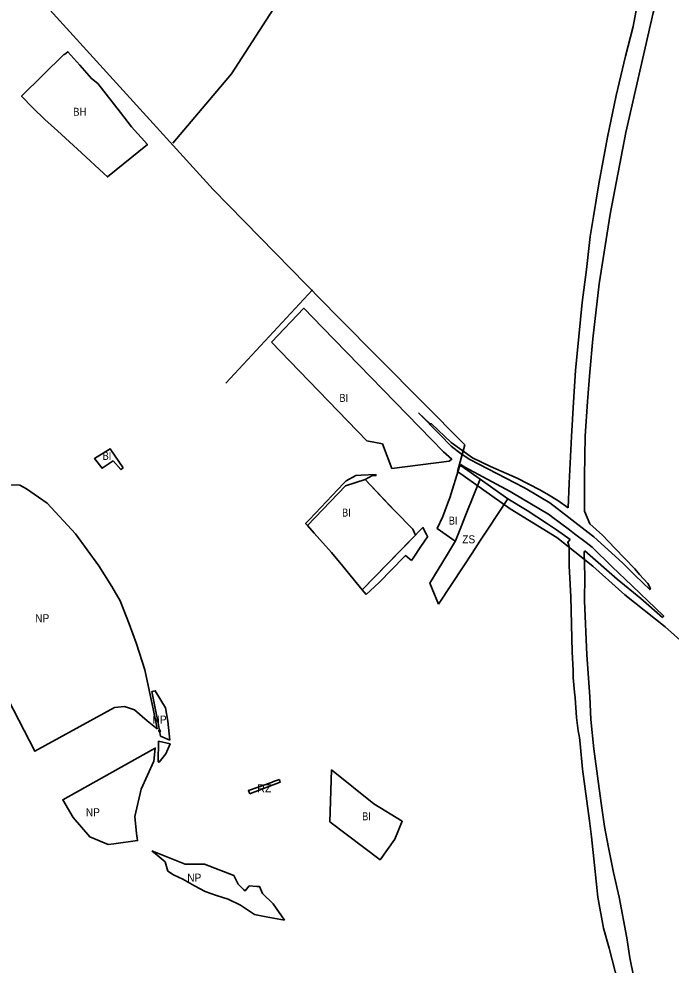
# Model space of a CAD drawing. Extents: x -650276 to -642489, y -1074311 to -1066658.
# Drawn here: x -646196 to -645218, y -1073124 to -1071706 of the extents above; entities that cross this region are included whole.
import ezdxf

# ---------------------------------------------------------------- set-up
doc = ezdxf.new("R2010")
doc.units = 0
doc.header["$LTSCALE"] = 4.8
doc.header["$PDMODE"] = 32
doc.header["$PDSIZE"] = 2.4
for name, color, linetype, lineweight in [('1', 7, 'Continuous', 35), ('15', 7, 'Continuous', 35), ('2', 7, 'Continuous', 35), ('24', 7, 'Continuous', 35), ('41', 7, 'Continuous', 35), ('48', 7, 'Continuous', 35), ('54', 7, 'Continuous', 35), ('6', 7, 'Continuous', 35)]:
    doc.layers.add(name, color=color, linetype=linetype, lineweight=lineweight)
doc.layers.add('62', color=7, linetype='Continuous')
doc.layers.add('63', color=7, linetype='Continuous')

msp = doc.modelspace()

# ---------------------------------------------------------------- linework, layer by layer
at = {"layer": '1'}
msp.add_lwpolyline([(-646102.04, -1071906.4), (-646068.317, -1071937.555), (-646062.91, -1071942.55), (-646002.93, -1071893.984), (-646026.64, -1071867.44), (-646043.49, -1071845.87), (-646077.32, -1071802.59), (-646087, -1071795), (-646104.5, -1071774.86), (-646122.16, -1071754.78), (-646127.12, -1071759.15), (-646127.84, -1071758.53), (-646191.57, -1071821.44), (-646174.69, -1071838.69), (-646156.59, -1071856.53), (-646137.74, -1071873.31)], close=True, dxfattribs=at)
at = {"layer": '15'}
for points in [[(-645661.3, -1072388.74), (-645682.59, -1072389.76), (-645690.37, -1072390.13), (-645705, -1072398.19), (-645708.94, -1072402.11)], [(-645676.53, -1072396.16), (-645676.53, -1072396.16), (-645665.32, -1072390.32), (-645660.16, -1072389.95), (-645661.3, -1072388.74)], [(-645708.94, -1072402.11), (-645760.02, -1072455.94), (-645765.95, -1072462.03), (-645763.06, -1072465.26)], [(-645763.06, -1072465.26), (-645706.039, -1072405.769), (-645676.53, -1072396.16)], [(-645582.84, -1072481.71), (-645584.46, -1072478.58), (-645589.862, -1072468.109), (-645680.87, -1072561.42), (-645675.13, -1072568.36)], [(-645607.07, -1072517.61), (-645605.95, -1072515.95), (-645604.82, -1072514.3), (-645592.9, -1072496.52), (-645583.13, -1072482.13), (-645582.84, -1072481.71)], [(-645675.13, -1072568.36), (-645655.65, -1072550.62), (-645617.87, -1072512.12), (-645615.95, -1072510.16), (-645607.07, -1072517.61)]]:
    msp.add_lwpolyline(points, dxfattribs=at)
at = {"layer": '2'}
msp.add_line((-645553.35, -1072508.1), (-645541.09, -1072487.98), dxfattribs=at)
for points in [[(-645817.219, -1072189.975), (-645768.649, -1072139.283), (-645740.45, -1072168.23), (-645559.34, -1072354.42), (-645546.82, -1072365.72), (-645550.41, -1072368.47), (-645636.37, -1072379.57), (-645650.78, -1072342.73), (-645674, -1072338), (-645789.298, -1072218.833)], [(-645729.36, -1072909.65), (-645654.16, -1072966.3), (-645632.23, -1072935.28), (-645620.92, -1072908.65), (-645663.52, -1072882.58), (-645726.9, -1072831.5)]]:
    msp.add_lwpolyline(points, close=True, dxfattribs=at)
for points in [[(-646039.16, -1072378.43), (-646058.64, -1072350.29), (-646082.55, -1072364.84), (-646071, -1072379.27), (-646054.43, -1072368.34)], [(-646054.43, -1072368.34), (-646042.65, -1072381.23), (-646039.16, -1072378.43)], [(-645541.09, -1072487.98), (-645533.15, -1072468.21), (-645524.87, -1072447.61), (-645503.98, -1072395.64), (-645532.75, -1072375.41), (-645535.05, -1072376.72), (-645549.6, -1072423.39), (-645551.54, -1072428.66), (-645559.92, -1072451.41), (-645568.38, -1072469.68), (-645541.56, -1072488.74)], [(-645632.1, -1072442.93), (-645676.53, -1072396.16), (-645706.039, -1072405.769), (-645763.06, -1072465.26), (-645753.128, -1072476.383), (-645744.38, -1072486.18), (-645726.95, -1072505.7), (-645709.92, -1072526.3), (-645694.51, -1072544.93), (-645680.87, -1072561.42), (-645600.883, -1072479.409)], [(-645632.1, -1072442.93), (-645638.82, -1072435.99), (-645676.53, -1072396.16), (-645706.039, -1072405.769), (-645763.06, -1072465.26), (-645753.128, -1072476.383)], [(-645600.945, -1072479.473), (-645605.17, -1072470.52), (-645632.1, -1072442.93)], [(-645753.128, -1072476.383), (-645744.38, -1072486.18), (-645726.95, -1072505.7), (-645709.92, -1072526.3)], [(-645709.92, -1072526.3), (-645694.51, -1072544.93), (-645680.87, -1072561.42), (-645600.945, -1072479.473)]]:
    msp.add_lwpolyline(points, dxfattribs=at)
at = {"layer": '24'}
for points in [[(-645339.904, -1072462.677), (-645347.551, -1072443.527), (-645347.677, -1072391.355), (-645346.62, -1072330.914), (-645343.458, -1072278.998), (-645339.908, -1072235.158), (-645335.367, -1072185.207), (-645325.498, -1072102.789), (-645309.01, -1071998.147), (-645285.617, -1071875.733), (-645244.798, -1071696.585), (-645235.793, -1071663.703), (-645230.436, -1071634.261), (-645227.905, -1071625.277), (-645222.48, -1071606.08)], [(-645339.904, -1072462.677), (-645347.551, -1072443.527), (-645347.677, -1072391.355), (-645346.62, -1072330.914), (-645343.458, -1072278.998), (-645339.908, -1072235.158), (-645335.367, -1072185.207), (-645325.498, -1072102.789), (-645309.01, -1071998.147), (-645285.617, -1071875.733), (-645244.798, -1071696.585), (-645235.793, -1071663.703), (-645230.436, -1071634.261), (-645227.905, -1071625.277), (-645222.48, -1071606.08)], [(-645255.662, -1071626.67), (-645261.094, -1071645.025), (-645264.841, -1071657.687), (-645269.077, -1071687.396), (-645274.868, -1071717.176), (-645286.175, -1071761.228), (-645300.076, -1071820.179), (-645313.153, -1071883.081), (-645326.343, -1071952.807)], [(-645255.662, -1071626.67), (-645261.094, -1071645.025), (-645264.841, -1071657.687), (-645269.077, -1071687.396), (-645274.868, -1071717.176), (-645286.175, -1071761.228), (-645300.076, -1071820.179), (-645313.153, -1071883.081)], [(-645313.153, -1071883.081), (-645326.343, -1071952.807), (-645334.118, -1072001.954), (-645339.455, -1072031.565), (-645344.819, -1072081.225), (-645351.358, -1072130.815), (-645361.317, -1072232.824), (-645364.435, -1072280.268), (-645366.951, -1072331.609), (-645370.624, -1072401.447), (-645372.228, -1072438.764)], [(-645326.343, -1071952.807), (-645334.118, -1072001.954), (-645339.455, -1072031.565), (-645344.819, -1072081.225), (-645351.358, -1072130.815), (-645361.317, -1072232.824), (-645364.435, -1072280.268), (-645366.951, -1072331.609), (-645370.624, -1072401.447), (-645372.228, -1072438.764)], [(-645372.228, -1072438.764), (-645387.894, -1072427.453), (-645401.441, -1072419.033), (-645414.631, -1072411.611), (-645448.831, -1072394.325), (-645488.64, -1072376.782), (-645515.437, -1072363.447), (-645547.593, -1072340.827), (-645577.33, -1072312.704), (-645579.217, -1072312.425), (-645596.405, -1072296.114)], [(-645596.405, -1072296.114), (-645564.4, -1072328.61), (-645547.72, -1072346.19), (-645532.07, -1072358.01), (-645531.65, -1072358.29), (-645528.27, -1072360.53), (-645519.57, -1072366.3), (-645438.64, -1072408.1)], [(-645372.228, -1072438.764), (-645387.894, -1072427.453), (-645401.441, -1072419.033), (-645414.631, -1072411.611), (-645448.831, -1072394.325), (-645488.64, -1072376.782), (-645515.437, -1072363.447), (-645547.593, -1072340.827), (-645577.33, -1072312.704), (-645579.217, -1072312.425), (-645596.405, -1072296.114)], [(-645596.405, -1072296.114), (-645564.4, -1072328.61), (-645547.72, -1072346.19), (-645532.07, -1072358.01), (-645531.65, -1072358.29), (-645528.27, -1072360.53), (-645519.57, -1072366.3), (-645438.64, -1072408.1)], [(-645462.646, -1072425.015), (-645503.98, -1072395.64), (-645532.75, -1072375.41), (-645534.3, -1072374.33), (-645533.08, -1072373.71)], [(-645533.08, -1072373.71), (-645527.33, -1072377.73), (-645459.31, -1072413.95), (-645456.52, -1072415.6), (-645400.12, -1072449.03), (-645396.94, -1072451.44), (-645370.226, -1072471.736)], [(-645438.64, -1072408.1), (-645437.6, -1072408.64), (-645434.19, -1072410.67), (-645399.77, -1072431.12), (-645371.356, -1072453.119), (-645342.284, -1072475.625)], [(-645438.64, -1072408.1), (-645437.6, -1072408.64), (-645434.19, -1072410.67), (-645399.77, -1072431.12), (-645371.356, -1072453.119), (-645342.284, -1072475.625), (-645333.62, -1072482.33), (-645290.76, -1072520.92)], [(-645369.364, -1072485.931), (-645389.731, -1072471.612), (-645404.64, -1072461.72), (-645433.91, -1072442.56), (-645462.646, -1072425.015)], [(-645370.226, -1072471.736), (-645362.81, -1072477.37), (-645345.079, -1072490.836)], [(-645290.76, -1072520.92), (-645271.74, -1072539.96), (-645249.9, -1072561.25), (-645248.967, -1072559.511), (-645252.768, -1072552.178), (-645265.009, -1072538.358), (-645272.276, -1072530.154), (-645302.303, -1072499.014), (-645320.805, -1072479.495), (-645339.904, -1072462.677)], [(-645290.76, -1072520.92), (-645271.74, -1072539.96), (-645249.9, -1072561.25), (-645248.967, -1072559.511), (-645252.768, -1072552.178), (-645265.009, -1072538.358), (-645272.276, -1072530.154), (-645302.303, -1072499.014), (-645320.805, -1072479.495), (-645339.904, -1072462.677)], [(-645364.524, -1072682.575), (-645366.022, -1072654.462), (-645368.173, -1072571.881), (-645370.755, -1072525.734), (-645370.928, -1072496.619), (-645372.72, -1072490.314), (-645369.364, -1072485.931)], [(-645342.284, -1072475.625), (-645333.62, -1072482.33), (-645290.76, -1072520.92)], [(-645347.292, -1072502.877), (-645348.253, -1072505.583), (-645347.214, -1072540.97), (-645347.795, -1072577.893), (-645344.152, -1072658.857), (-645339.96, -1072721.587), (-645338.023, -1072755.969), (-645333.718, -1072799.987)], [(-645230.845, -1072602.888), (-645263.217, -1072574.314), (-645298.498, -1072545.352), (-645347.292, -1072502.877)], [(-645345.079, -1072490.836), (-645336.33, -1072497.48), (-645306.46, -1072527.08), (-645276.93, -1072555.11), (-645263.7, -1072567.8), (-645242, -1072588.6), (-645241.87, -1072588.722), (-645228.96, -1072600.865), (-645230.845, -1072602.888)], [(-645357.272, -1072772.771), (-645359.76, -1072752.865), (-645361.874, -1072723.527), (-645362.708, -1072714.781), (-645364.786, -1072692.977), (-645364.524, -1072682.575)], [(-645271.518, -1073261.16), (-645272.747, -1073256.762), (-645275.269, -1073240.71), (-645276.125, -1073226.571), (-645288.647, -1073184.518), (-645297.395, -1073151.294), (-645310.558, -1073098.946), (-645319.052, -1073068.6), (-645327.554, -1073022.214), (-645332.517, -1072974.538), (-645337.34, -1072932.073), (-645340.345, -1072908.029), (-645350.822, -1072830.388), (-645354.019, -1072792.454), (-645355.121, -1072782.993), (-645357.272, -1072772.771)], [(-645333.718, -1072799.987), (-645327.091, -1072848.387), (-645322.284, -1072885.085), (-645317.65, -1072916.642)], [(-645317.65, -1072916.642), (-645311.772, -1072947.945), (-645304.24, -1072985.372), (-645295.788, -1073022.556)], [(-645295.788, -1073022.556), (-645284.269, -1073083.286), (-645279.878, -1073113.356), (-645262.388, -1073199.409), (-645257.842, -1073221.36), (-645247.051, -1073248.736), (-645239.9, -1073270.025), (-645226.847, -1073278.345), (-645227.199, -1073283.366), (-645227.744, -1073292.736)]]:
    msp.add_lwpolyline(points, dxfattribs=at)
at = {"layer": '41'}
msp.add_line((-645566.54, -1072582.88), (-645528.81, -1072525.54), dxfattribs=at)
msp.add_lwpolyline([(-645528.81, -1072525.54), (-645516.37, -1072506.64), (-645504.48, -1072488.58), (-645492.61, -1072470.54), (-645462.65, -1072425.01), (-645503.98, -1072395.64), (-645524.87, -1072447.61), (-645533.15, -1072468.21), (-645541.09, -1072487.98), (-645553.35, -1072508.1), (-645579.76, -1072551.45), (-645575.9, -1072560.13), (-645566.54, -1072582.88)], dxfattribs=at)
at = {"layer": '48'}
for points in [[(-646236.97, -1072678.31), (-646171.72, -1072803.51), (-646052.58, -1072737.82), (-646037.23, -1072736.38), (-646022.4, -1072741.58), (-646003.22, -1072757.85), (-645988.43, -1072769.93), (-645990.04, -1072761.78), (-645993.89, -1072742.23), (-646006.66, -1072681.4), (-646019.16, -1072642.35), (-646030.17, -1072612.31), (-646043.87, -1072578.12), (-646056.42, -1072556.49), (-646075.82, -1072525.54), (-646110.61, -1072477.49), (-646153.49, -1072431.54), (-646172.81, -1072418.2), (-646184.449, -1072410.256), (-646194.19, -1072404.62), (-646254.75, -1072404.25)], [(-645969.46, -1072787.03), (-645972.31, -1072758.48), (-645975.86, -1072738.61), (-645991.31, -1072712.86), (-645996.31, -1072714.11), (-645990.95, -1072741.65), (-645987.1, -1072761.2), (-645984.79, -1072772.91)], [(-645984.79, -1072772.91), (-645983.22, -1072780.88), (-645969.46, -1072787.03)], [(-645986.24, -1072788.33), (-645986.71, -1072819.26), (-645986.71, -1072819.26)], [(-645975.3, -1072807.37), (-645969.01, -1072792.28), (-645986.24, -1072788.33)], [(-645986.71, -1072819.26), (-645986.71, -1072819.26), (-645985.19, -1072819.72), (-645975.3, -1072807.37)], [(-645972.6, -1072983.41), (-645976.48, -1072969.55), (-645988.49, -1072959.28), (-645996.2, -1072952.69)], [(-645996.2, -1072952.69), (-645946.4, -1072973.05), (-645917.53, -1072972.93), (-645873.3, -1072989.79), (-645866.93, -1073002.72)], [(-645863.39, -1073034.25), (-645882.07, -1073025.22), (-645899.35, -1073019.65), (-645916.47, -1073014.03), (-645932.44, -1073005.5), (-645949.85, -1072995.57), (-645962.81, -1072989.45), (-645963.77, -1072989), (-645972.6, -1072983.41)], [(-645866.93, -1073002.72), (-645858.82, -1073010.74), (-645856.46, -1073013.07), (-645850.37, -1073005.42), (-645838.89, -1073006.18)], [(-645838.89, -1073006.18), (-645834.9, -1073006.45), (-645830.6, -1073016.92), (-645814.27, -1073032.11), (-645797.32, -1073056.62)], [(-645797.32, -1073056.62), (-645824.93, -1073051.83), (-645842.53, -1073048.19), (-645863.39, -1073034.25)]]:
    msp.add_lwpolyline(points, dxfattribs=at)
msp.add_lwpolyline([(-645993.47, -1072818.44), (-645991.37, -1072798.84), (-645996.8, -1072801.88), (-646129.91, -1072876.24), (-646114.5, -1072902.8), (-646089.39, -1072931.92), (-646062.04, -1072943.58), (-646053.287, -1072942.399), (-646017.65, -1072937.59), (-646019.21, -1072926.91), (-646021.64, -1072901.6), (-646012.37, -1072860.3)], close=True, dxfattribs=at)
msp.add_point((-645984.79, -1072772.91), dxfattribs=at)
at = {"layer": '54'}
msp.add_line((-645885.363, -1072251.506), (-645755.385, -1072111.972), dxfattribs=at)
for points in [[(-645648.577, -1071395.44), (-645803.784, -1071674.386), (-645877, -1071788), (-645965, -1071892)], [(-646336.784, -1071524.232), (-646218.737, -1071612.767), (-646164.374, -1071674.897), (-645904.456, -1071961.331), (-645718.199, -1072151.712), (-645526.944, -1072343.922), (-645538, -1072384), (-645459, -1072440), (-645389, -1072483), (-645335, -1072526), (-645287, -1072569), (-645227, -1072617), (-645139.573, -1072694.628), (-645084.365, -1072788.086)]]:
    msp.add_lwpolyline(points, dxfattribs=at)
at = {"layer": '6'}
for points in [[(-645834.208, -1072856.314), (-645837.027, -1072857.313), (-645839.908, -1072858.343), (-645842.74, -1072859.344), (-645845.619, -1072860.364), (-645848.628, -1072861.433), (-645851.48, -1072862.586), (-645850.187, -1072866.251), (-645850.17, -1072866.3), (-645849.705, -1072867.618), (-645849.703, -1072867.622)], [(-645849.703, -1072867.622), (-645848.52, -1072867.16), (-645803.84, -1072849.72), (-645805.159, -1072845.994)], [(-645805.159, -1072845.994), (-645808.177, -1072847.063), (-645811.148, -1072848.124), (-645813.978, -1072849.124), (-645816.948, -1072850.184), (-645819.779, -1072851.184), (-645822.726, -1072852.233), (-645825.527, -1072853.233), (-645828.409, -1072854.254), (-645834.208, -1072856.314)]]:
    msp.add_lwpolyline(points, dxfattribs=at)

# ---------------------------------------------------------------- texts
at = {"layer": '62'}
for s, width, p in [('BH', 0.9, (-646114.48, -1071850.818)), ('BI', 0.85, (-645715.06, -1072279.771)), ('BI', 0.85, (-645711.104, -1072451.727)), ('BI', 0.85, (-645551.06, -1072463.771)), ('ZS', 0.95, (-645531.06, -1072491.771)), ('NP', 0.95, (-646171.335, -1072610.048)), ('NP', 0.95, (-646095.335, -1072901.048)), ('BI', 0.85, (-645681, -1072907.167)), ('NP', 0.95, (-645943.335, -1072999.048))]:
    msp.add_text(s, height=12, dxfattribs=dict(at, width=width)).set_placement(p)
msp.add_text('RZ', height=12, dxfattribs=at).set_placement((-645838.415, -1072865.224))
at = {"layer": '63'}
for s, width, p in [('BI', 0.85, (-646070.104, -1072366.727)), ('NP', 0.95, (-645995.335, -1072762.048))]:
    msp.add_text(s, height=12, dxfattribs=dict(at, width=width)).set_placement(p)

doc.saveas('drawing.dxf')
